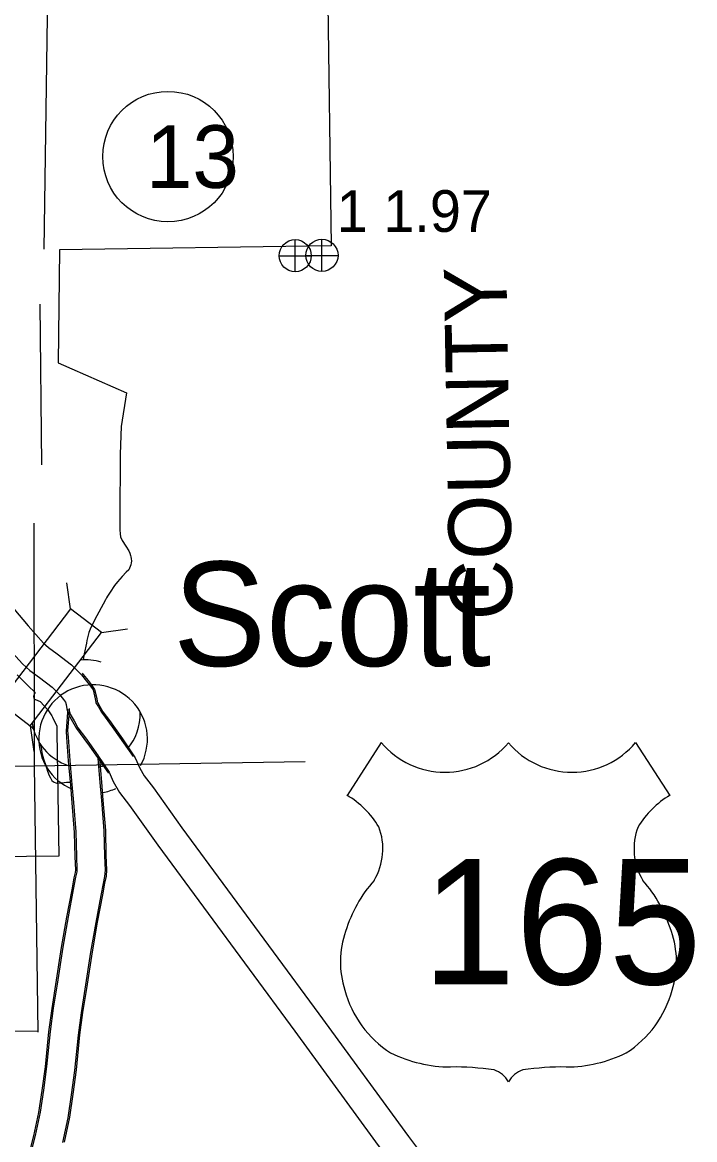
# Model space of a CAD drawing. Extents: x 1127717 to 1741049, y 2026793 to 2244711.
# Drawn here: x 1246182 to 1249585, y 2127719 to 2133375 of the extents above; entities that cross this region are included whole.
import ezdxf

# ---------------------------------------------------------------- set-up
doc = ezdxf.new("R2010")
doc.units = 0
for name, color, linetype in [('10', 7, 'Continuous'), ('15', 7, 'Continuous'), ('2', 7, 'Continuous'), ('20', 7, 'Continuous'), ('22', 7, 'Continuous'), ('24', 7, 'Continuous'), ('25', 7, 'Continuous'), ('26', 7, 'Continuous'), ('27', 7, 'Continuous'), ('30', 7, 'Continuous'), ('5', 7, 'Continuous'), ('6', 7, 'Continuous'), ('9', 7, 'Continuous')]:
    doc.layers.add(name, color=color, linetype=linetype)

msp = doc.modelspace()

# ---------------------------------------------------------------- linework, layer by layer
at = {"layer": '10'}
for points in [[(1246410.8, 2129898.7), (1246411.3, 2129882.2), (1246403.9, 2129787.4), (1246406, 2129754.8), (1246414.5, 2129636.5), (1246425.5, 2129513.7), (1246433.1, 2129423.7), (1246444.8, 2129274), (1246447.9, 2129150.7), (1246450.7, 2129085.6), (1246449.6, 2129072), (1246443.8, 2129045), (1246432.5, 2128982.8), (1246406, 2128845), (1246379.2, 2128691.6), (1246350.5, 2128504.5), (1246331, 2128382.1), (1246315.1, 2128264.8), (1246297.2, 2128087), (1246281, 2127967.5), (1246264.7, 2127856.1), (1246239.7, 2127738.1), (1246212.2, 2127631.6)], [(1246418.6, 2129901), (1246419.1, 2129884.5), (1246411.7, 2129789.7), (1246413.9, 2129757.1), (1246422.3, 2129638.8), (1246433.4, 2129515.9), (1246441, 2129426), (1246452.7, 2129276.3), (1246455.7, 2129153), (1246458.6, 2129087.9), (1246457.5, 2129074.3), (1246451.7, 2129047.3), (1246440.4, 2128985.1), (1246413.8, 2128847.3), (1246387, 2128693.9), (1246358.4, 2128506.7), (1246338.9, 2128384.4), (1246322.9, 2128267.1), (1246305.1, 2128089.3), (1246288.9, 2127969.8), (1246272.6, 2127858.4), (1246247.5, 2127740.4), (1246220, 2127633.9)], [(1246563.5, 2129654.9), (1246564, 2129648.6), (1246575, 2129526.7), (1246582.6, 2129435.8), (1246594.7, 2129281.7), (1246597.8, 2129155.8), (1246601, 2129082.9), (1246598.4, 2129050.3), (1246591, 2129015.8), (1246579.9, 2128955.2), (1246553.5, 2128817.9), (1246527.2, 2128667.4), (1246498.7, 2128481.3), (1246479.4, 2128360.2), (1246464.1, 2128247.2), (1246446.2, 2128069.4), (1246429.5, 2127946.6), (1246412.5, 2127829.6), (1246385.7, 2127703.7)], [(1246572.1, 2129648.3), (1246582.8, 2129529), (1246590.5, 2129438.1), (1246602.5, 2129284), (1246605.7, 2129158.1), (1246608.8, 2129085.2), (1246606.2, 2129052.5), (1246598.8, 2129018.1), (1246587.8, 2128957.4), (1246561.4, 2128820.2), (1246535.1, 2128669.7), (1246506.6, 2128483.6), (1246487.2, 2128362.4), (1246471.9, 2128249.5), (1246454.1, 2128071.7), (1246437.4, 2127948.8), (1246420.3, 2127831.9), (1246393.6, 2127706)]]:
    msp.add_lwpolyline(points, dxfattribs=at)
at = {"layer": '15'}
for points in [[(1246139.4, 2130405.9), (1246212.7, 2130319.6), (1246290, 2130232.8), (1246315.3, 2130209.6), (1246358.5, 2130178.4), (1246431.7, 2130122.5), (1246455.2, 2130099.7), (1246482, 2130072.1), (1246507.8, 2130040.2), (1246522.8, 2130021.1), (1246540.6, 2129995.9), (1246551.4, 2129950.4), (1246554, 2129934.3), (1246555, 2129930.9), (1246567.5, 2129909.5), (1246582.2, 2129882.4), (1246615.3, 2129838.5), (1246644.6, 2129797.3), (1246742.7, 2129657.8)], [(1246099.5, 2130221.1), (1246183.1, 2130127.3), (1246220.4, 2130093.2), (1246269, 2130058), (1246333.6, 2130008.7), (1246349.1, 2129993.6), (1246369.7, 2129972.5), (1246390.5, 2129946.7), (1246401.4, 2129932.9), (1246404.2, 2129920.9), (1246407.6, 2129900.2), (1246416.5, 2129870.7), (1246436.7, 2129836), (1246455.7, 2129801), (1246494.2, 2129749.9), (1246522.1, 2129710.6), (1246618, 2129574.3)], [(1246484.4, 2130080), (1246489.9, 2130074.4), (1246515.7, 2130042.4), (1246530.6, 2130023.4), (1246548.4, 2129998.2), (1246559.2, 2129952.7), (1246561.9, 2129936.5), (1246562.9, 2129933.2), (1246575.3, 2129911.8), (1246590, 2129884.7), (1246623.1, 2129840.8), (1246652.4, 2129799.5), (1246688.5, 2129748.4)], [(1246417.5, 2129895.8), (1246424.4, 2129873), (1246444.5, 2129838.3), (1246463.5, 2129803.3), (1246502.1, 2129752.2), (1246530, 2129712.9), (1246565.8, 2129662)], [(1246689.3, 2129747.1), (1246753.4, 2129652.1), (1246776.3, 2129600), (1246799.5, 2129560), (1246845.9, 2129500.5), (1246989.9, 2129297.3), (1247682.5, 2128356.4), (1248136.2, 2127734.8), (1248263.6, 2127566.8)], [(1246565, 2129663.2), (1246621.5, 2129579.4), (1246642.3, 2129532.1), (1246674.8, 2129475.9), (1246725.5, 2129410.9), (1246868.3, 2129209.5), (1247561.5, 2128267.7), (1248015.8, 2127645.2)]]:
    msp.add_lwpolyline(points, dxfattribs=at)
at = {"layer": '2'}
msp.add_lwpolyline([(1247726, 2133591.9), (1247745.1, 2132243.6), (1246370.9, 2132222.7), (1246363.4, 2131651.2), (1246710.2, 2131499.8), (1246682.1, 2131328.2), (1246678, 2131189.4), (1246676.3, 2130861.7), (1246675.2, 2130805.6), (1246676.9, 2130784.8), (1246679.7, 2130769.7), (1246687.2, 2130752.7), (1246706.9, 2130723.7), (1246720.7, 2130700.3), (1246726.9, 2130688.5), (1246730.4, 2130675.9), (1246731.7, 2130669.2), (1246733.6, 2130660.3), (1246734.1, 2130647.5), (1246733.5, 2130638.2), (1246731.4, 2130628.6), (1246725.4, 2130612.1), (1246720.5, 2130604.1), (1246708.3, 2130591.6), (1246688, 2130568.9), (1246663.6, 2130542.4), (1246649, 2130523.5), (1246626.4, 2130490.2), (1246613, 2130470.1), (1246607.9, 2130461.1), (1246603.3, 2130451.2), (1246546.9, 2130348.9), (1246525.2, 2130303.2), (1246519.2, 2130285.4), (1246516.9, 2130279.8), (1246509.1, 2130245.6), (1246506.4, 2130232.7), (1246495, 2130177.9), (1246489.6, 2130147.3)], dxfattribs=at)
at = {"layer": '20'}
for p, q in [((1246425.6, 2130406.4), (1246408, 2130537.3)), ((1246583, 2130286.3), (1246713.8, 2130303.9)), ((1246222.7, 2129814.1), (1246240.3, 2129683.3))]:
    msp.add_line(p, q, dxfattribs=at)
msp.add_lwpolyline([(1246222.7, 2129814.1), (1246583, 2130286.3), (1246425.6, 2130406.4), (1246065.3, 2129934.2)], close=True, dxfattribs=at)
at = {"layer": '22'}
for p, q in [((1247998.9, 2129728.8), (1247825.8, 2129461.1)), ((1249285.8, 2129728.8), (1249458.9, 2129461.1))]:
    msp.add_line(p, q, dxfattribs=at)
for centre, radius, start, end in [((1248321.2, 2129999.9), 421.2, 220.075, 319.6701), ((1248963.5, 2129999.9), 421.2, 220.3299, 319.925), ((1247599.7, 2129072.5), 449.7, 30.7809, 59.9883), ((1249685, 2129072.5), 449.7, 120.0117, 149.2191), ((1247698.6, 2129191.1), 308.3, 328.8105, 21.2108), ((1249586.1, 2129191.1), 308.3, 158.7892, 211.1895), ((1248504.7, 2128559.2), 719.2, 138.9565, 162.6913), ((1248780, 2128559.2), 719.2, 17.3087, 41.0435), ((1248267.3, 2128618.1), 475.2, 160.9576, 197.3819), ((1249017.4, 2128618.1), 475.2, 342.6181, 19.0424), ((1248344.7, 2128619.5), 549.9, 195.1074, 237.1312), ((1248940, 2128619.5), 549.9, 302.8688, 344.8926), ((1248354.9, 2128792.7), 706, 244.0771, 269.5779), ((1248929.8, 2128792.7), 706, 270.4221, 295.9229), ((1248371.2, 2126793.5), 1293.3, 81.1942, 90.9539), ((1248533, 2127953.1), 123.9, 28.0342, 72.9864), ((1248751.7, 2127953.1), 123.9, 107.0136, 151.9658), ((1248913.5, 2126793.5), 1293.3, 89.0461, 98.8058)]:
    msp.add_arc(centre, radius, start, end, dxfattribs=at)
at = {"layer": '24'}
for centre, start, end in [((1246503.4, 2129872.6), 73.3807, 95.8922), ((1246540.4, 2129746.6), 330.733, 246.9867), ((1246503.4, 2129872.6), 320.3322, 1.7396), ((1246503.4, 2129872.6), 189.0982, 251.1797), ((1246503.4, 2129872.6), 283.7891, 288.6769), ((1246540.4, 2129746.6), 280.4786, 294.8874)]:
    msp.add_arc(centre, 275, start, end, dxfattribs=at)
at = {"layer": '26'}
for p, q in [((1247563.4, 2132112.3), (1247563.4, 2132274.8)), ((1247698.6, 2132114.1), (1247698.6, 2132276.6)), ((1247482.2, 2132193.6), (1247644.7, 2132193.6)), ((1247617.4, 2132195.4), (1247779.9, 2132195.4))]:
    msp.add_line(p, q, dxfattribs=at)
for centre in [(1247563.4, 2132193.6), (1247698.6, 2132195.4)]:
    msp.add_circle(centre, 81.2, dxfattribs=at)
at = {"layer": '27'}
msp.add_circle((1246919.4, 2132695.3), 330, dxfattribs=at)
at = {"layer": '5'}
for points in [[(1246292.8, 2132227), (1246310.7, 2133522), (1246312.6, 2134233)], [(1246281.2, 2131134.6), (1246273.2, 2131948.2)], [(1246240, 2130840.3), (1246242.1, 2129613.8), (1246261.1, 2128262.7)], [(1244913.3, 2129607.7), (1246241.2, 2129611.8), (1247614, 2129633.3)], [(1245705.4, 2128263.4), (1246259.1, 2128270.2)]]:
    msp.add_lwpolyline(points, dxfattribs=at)
at = {"layer": '6'}
msp.add_lwpolyline([(1246156.6, 2130071.9), (1246211.7, 2130017), (1246247.1, 2129981.7), (1246243.7, 2129976.7), (1246239.1, 2129961.7), (1246241.9, 2129947), (1246248.6, 2129946.8), (1246272.5, 2129937.6), (1246311.7, 2129894.5), (1246331.8, 2129863.9), (1246335.4, 2129858.4), (1246357.7, 2129812.8), (1246357.4, 2129779.9), (1246367, 2129154.1), (1245708.7, 2129147.4)], dxfattribs=at)
at = {"layer": '9'}
for points in [[(1246219.2, 2129815.2), (1246228.9, 2129808.8), (1246238.5, 2129796.5)], [(1246273.1, 2129721.7), (1246277.3, 2129706), (1246279.2, 2129690), (1246283.3, 2129669.6), (1246289.9, 2129646.8), (1246301.9, 2129613.6), (1246310.2, 2129584.8), (1246317.4, 2129561.9), (1246324.2, 2129550.1), (1246331.5, 2129537.3), (1246340.2, 2129530), (1246354.9, 2129523), (1246375.3, 2129525.6), (1246393.3, 2129526.6), (1246406.2, 2129529), (1246422.1, 2129528.9), (1246423.2, 2129528.4)]]:
    msp.add_lwpolyline(points, dxfattribs=at)

# ---------------------------------------------------------------- texts
at = {"layer": '22'}
msp.add_text('165', height=633.6, dxfattribs=at).set_placement((1248206.5, 2128505.2))
at = {"layer": '24'}
msp.add_text('Scott', height=528, dxfattribs=at).set_placement((1246944.6, 2130116.7))
at = {"layer": '25'}
msp.add_text('1 1.97', height=211.2, dxfattribs=at).set_placement((1247773.6, 2132314))
at = {"layer": '27'}
msp.add_text('13', height=316.8, dxfattribs=at).set_placement((1246807.2, 2132536.9))
at = {"layer": '30'}
msp.add_text('COUNTY', height=316.8, rotation=91, dxfattribs=at).set_placement((1248662.9, 2130351.2))

doc.saveas('drawing.dxf')
